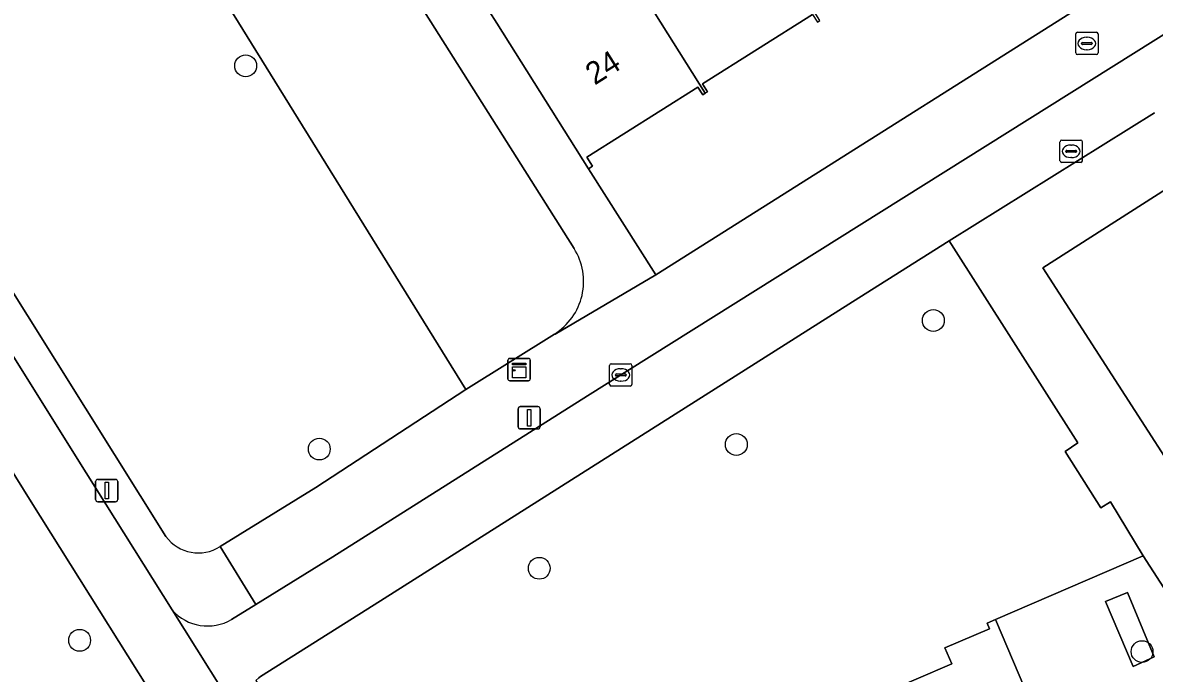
# Model space of a CAD drawing. Extents: x 160077 to 160948, y 386481 to 387498.
# Drawn here: x 160333.6 to 160384.3, y 386943.1 to 386972.2 of the extents above; entities that cross this region are included whole.
import ezdxf

# ---------------------------------------------------------------- set-up
doc = ezdxf.new("R2010")
doc.units = 0
for name, color, linetype in [('IMGEO_Berm_groen', 7, 'Continuous'), ('IMGEO_Boom', 7, 'Continuous'), ('IMGEO_Brandkraan', 7, 'Continuous'), ('IMGEO_Erf', 7, 'Continuous'), ('IMGEO_Fietspad_gesloten', 7, 'Continuous'), ('IMGEO_Fietspad_open', 7, 'Continuous'), ('IMGEO_Groenvoorziening', 7, 'Continuous'), ('IMGEO_Kast', 7, 'Continuous'), ('IMGEO_Kolk', 7, 'Continuous'), ('IMGEO_Lichtmast', 7, 'Continuous'), ('IMGEO_Pand', 7, 'Continuous'), ('IMGEO_Pand_nummerreeks', 7, 'Continuous'), ('IMGEO_Parkeervlak_open', 7, 'Continuous'), ('IMGEO_Rioolput', 7, 'Continuous'), ('IMGEO_Voetpad_open', 7, 'Continuous')]:
    doc.layers.add(name, color=color, linetype=linetype)

msp = doc.modelspace()

# ---------------------------------------------------------------- linework, layer by layer
at = {"layer": 'IMGEO_Berm_groen'}
msp.add_lwpolyline([(160381.755, 386874.497), (160381.719, 386874.568), (160381.199, 386875.409), (160373.722, 386887.333), (160362.991, 386904.447), (160352.34, 386921.431), (160340.92, 386939.644), (160333.952, 386950.749), (160331.8, 386954.187), (160320.577, 386972.116)], dxfattribs=at)
at = {"layer": 'IMGEO_Boom'}
for centre in [(160343.561, 386970.285), (160374.386, 386958.878), (160365.556, 386953.322), (160346.862, 386953.117), (160356.722, 386947.777), (160336.119, 386944.55), (160383.742, 386944.046)]:
    msp.add_circle(centre, 0.489, dxfattribs=at)
at = {"layer": 'IMGEO_Brandkraan'}
for p, q in [((160380.767, 386970.859), (160380.767, 386971.711)), ((160380.842, 386971.785), (160381.694, 386971.785)), ((160381.255, 386971.565), (160381.28, 386971.565)), ((160381.768, 386971.711), (160381.768, 386970.859)), ((160381.026, 386971.279), (160381.026, 386971.291)), ((160381.464, 386971.242), (160381.066, 386971.242)), ((160381.069, 386971.328), (160381.467, 386971.328)), ((160381.51, 386971.291), (160381.51, 386971.279)), ((160381.694, 386970.785), (160380.842, 386970.785)), ((160381.278, 386971.005), (160381.253, 386971.005))]:
    msp.add_line(p, q, dxfattribs=at)
for points in [[(160380.767, 386970.859), (160380.767, 386971.711)], [(160380.842, 386971.785), (160381.694, 386971.785)], [(160381.768, 386971.711), (160381.768, 386970.859)], [(160381.694, 386970.785), (160380.842, 386970.785)]]:
    msp.add_lwpolyline(points, dxfattribs=at)
for centre, radius, start, end in [((160380.844, 386971.709), 0.0765, 91.552, 178.448), ((160380.844, 386971.709), 0.0765, 91.552, 178.448), ((160381.692, 386971.709), 0.0765, 1.552, 88.448), ((160381.692, 386971.709), 0.0765, 1.552, 88.448), ((160381.066, 386971.288), 0.0403, 85.8775, 175.7526), ((160381.063, 386971.278), 0.0366, 178.938, 274.7102), ((160381.467, 386971.285), 0.043, 264.8664, 352.4533), ((160381.471, 386971.29), 0.0386, 1.7309, 96.639), ((160380.844, 386970.861), 0.0765, 181.552, 268.448), ((160380.844, 386970.861), 0.0765, 181.552, 268.448), ((160381.692, 386970.861), 0.0765, 271.552, 358.448), ((160381.692, 386970.861), 0.0765, 271.552, 358.448)]:
    msp.add_arc(centre, radius, start, end, dxfattribs=at)
for centre, major_axis, ratio, start_param, end_param in [((160381.254, 386971.285), (-0.387, 0.002), 0.722429, 4.712389, 7.853982), ((160381.279, 386971.285), (-0.39, 0.002), 0.717154, 1.570796, 4.712389)]:
    msp.add_ellipse(centre, major_axis=major_axis, ratio=ratio, start_param=start_param, end_param=end_param, dxfattribs=at)
at = {"layer": 'IMGEO_Erf'}
msp.add_lwpolyline([(160368.975, 386972.582), (160364.044, 386969.481), (160364.27, 386969.122), (160364.16, 386969.052), (160364.05, 386968.983), (160363.836, 386969.323), (160358.855, 386966.191), (160359.108, 386965.789), (160358.927, 386965.675), (160361.943, 386960.929), (160386.133, 386976.2)], dxfattribs=at)
at = {"layer": 'IMGEO_Fietspad_gesloten'}
for points in [[(160298.634, 387007.207), (160300.211, 387004.626), (160309.459, 386989.877), (160320.577, 386972.116), (160331.8, 386954.187), (160333.952, 386950.749), (160340.92, 386939.644), (160352.34, 386921.431), (160362.991, 386904.447), (160373.722, 386887.333), (160381.199, 386875.409), (160381.719, 386874.568), (160381.755, 386874.497), (160383.65, 386871.599), (160379.535, 386869.036)], [(160384.718, 386875.882), (160383.32, 386877.321), (160343.718, 386940.41), (160343.653, 386940.514), (160340.267, 386945.91), (160336.414, 386952.059), (160311.846, 386991.299)]]:
    msp.add_lwpolyline(points, dxfattribs=at)
at = {"layer": 'IMGEO_Fietspad_open'}
for points in [[(160392.767, 386976.747), (160358.891, 386955.508), (160347.47, 386948.297), (160344.021, 386946.162), (160342.931, 386945.487)], [(160371.041, 386959.892), (160375.091, 386962.445), (160384.296, 386968.171)], [(160344.012, 386942.759), (160344.15, 386942.871), (160344.231, 386942.938), (160349.319, 386946.138), (160371.041, 386959.892)], [(160340.267, 386945.91), (160343.653, 386940.514)]]:
    msp.add_lwpolyline(points, dxfattribs=at)
msp.add_arc((160341.854, 386947.307), 2.114, 221.3456, 300.6098, dxfattribs=at)
at = {"layer": 'IMGEO_Groenvoorziening'}
for points in [[(160334.305, 387000.002), (160333.091, 387001.929), (160330.043, 387000), (160327.145, 386998.17), (160353.425, 386955.793), (160357.402, 386958.269)], [(160358.281, 386962.101), (160334.305, 387000.002)], [(160327.145, 386998.17), (160319.488, 386993.382), (160314.349, 386990.13), (160337.688, 386952.871), (160339.984, 386949.196)], [(160342.413, 386948.748), (160346.707, 386951.396), (160353.425, 386955.793), (160327.145, 386998.17)], [(160382.328, 386950.748), (160381.9, 386950.487), (160380.291, 386953.014), (160380.863, 386953.4), (160375.091, 386962.445), (160371.041, 386959.892), (160349.319, 386946.138), (160344.231, 386942.938), (160344.15, 386942.871), (160344.012, 386942.759), (160385.024, 386877.426)], [(160387.832, 386876.495), (160402.136, 386879.409), (160401.949, 386880.328), (160396.287, 386879.166), (160394.179, 386884.089), (160389.777, 386882.204), (160367.51, 386934.196), (160372.585, 386936.369), (160370.414, 386941.438), (160375.213, 386943.493), (160374.906, 386944.211), (160376.91, 386945.068), (160376.8, 386945.325), (160377.168, 386945.482), (160383.799, 386948.34), (160382.328, 386950.748)]]:
    msp.add_lwpolyline(points, dxfattribs=at)
for centre, radius, start, end in [((160355.937, 386960.622), 2.771, 301.9024, 32.2591), ((160341.443, 386950.295), 1.827, 217.0074, 302.0924)]:
    msp.add_arc(centre, radius, start, end, dxfattribs=at)
at = {"layer": 'IMGEO_Kast'}
for p, q in [((160355.32, 386956.254), (160355.32, 386957.095)), ((160355.32, 386957.095), (160355.32, 386956.254)), ((160355.395, 386957.179), (160356.236, 386957.179)), ((160356.236, 386957.179), (160355.395, 386957.179)), ((160356.32, 386957.104), (160356.32, 386956.263)), ((160356.32, 386956.263), (160356.32, 386957.104)), ((160356.245, 386956.179), (160355.404, 386956.179)), ((160355.404, 386956.179), (160356.245, 386956.179))]:
    msp.add_line(p, q, dxfattribs=at)
for points in [[(160355.515, 386956.969), (160356.115, 386956.969), (160356.115, 386956.884), (160355.515, 386956.884), (160355.515, 386956.969)], [(160355.515, 386956.794), (160356.115, 386956.794), (160356.115, 386956.305), (160355.515, 386956.305), (160355.515, 386956.794)]]:
    msp.add_lwpolyline(points, dxfattribs=at)
msp.add_circle((160355.599, 386956.643), 0.0377, dxfattribs=at)
for centre, start, end in [((160355.398, 386957.101), 92.4484, 184.2845), ((160355.398, 386957.101), 92.4484, 184.2845), ((160356.242, 386957.101), 2.4484, 94.2845), ((160356.242, 386957.101), 2.4484, 94.2845), ((160355.398, 386956.257), 182.4484, 274.2845), ((160355.398, 386956.257), 182.4484, 274.2845), ((160356.242, 386956.257), 272.4484, 4.2845), ((160356.242, 386956.257), 272.4484, 4.2845)]:
    msp.add_arc(centre, 0.0779, start, end, dxfattribs=at)
at = {"layer": 'IMGEO_Kolk'}
for p, q in [((160359.875, 386956.012), (160359.875, 386956.864)), ((160359.95, 386956.938), (160360.802, 386956.938)), ((160360.876, 386956.864), (160360.876, 386956.012)), ((160360.134, 386956.432), (160360.134, 386956.444)), ((160360.572, 386956.395), (160360.174, 386956.395)), ((160360.177, 386956.481), (160360.575, 386956.481)), ((160360.363, 386956.718), (160360.388, 386956.718)), ((160360.618, 386956.444), (160360.618, 386956.432)), ((160360.802, 386955.938), (160359.95, 386955.938)), ((160360.386, 386956.158), (160360.361, 386956.158))]:
    msp.add_line(p, q, dxfattribs=at)
for points in [[(160359.875, 386956.012), (160359.875, 386956.864)], [(160359.95, 386956.938), (160360.802, 386956.938)], [(160360.876, 386956.864), (160360.876, 386956.012)], [(160360.802, 386955.938), (160359.95, 386955.938)]]:
    msp.add_lwpolyline(points, dxfattribs=at)
for centre, radius, start, end in [((160359.952, 386956.862), 0.0765, 91.552, 178.448), ((160359.952, 386956.862), 0.0765, 91.552, 178.448), ((160360.8, 386956.862), 0.0765, 1.552, 88.448), ((160360.8, 386956.862), 0.0765, 1.552, 88.448), ((160360.174, 386956.441), 0.0403, 85.8775, 175.7526), ((160360.171, 386956.431), 0.0366, 178.938, 274.7102), ((160360.575, 386956.438), 0.043, 264.8664, 352.4533), ((160360.579, 386956.443), 0.0386, 1.7309, 96.639), ((160359.952, 386956.014), 0.0765, 181.552, 268.448), ((160359.952, 386956.014), 0.0765, 181.552, 268.448), ((160360.8, 386956.014), 0.0765, 271.552, 358.448), ((160360.8, 386956.014), 0.0765, 271.552, 358.448)]:
    msp.add_arc(centre, radius, start, end, dxfattribs=at)
for centre, major_axis, ratio, start_param, end_param in [((160360.362, 386956.438), (-0.387, 0.002), 0.722429, 4.712389, 7.853982), ((160360.387, 386956.438), (-0.39, 0.002), 0.717154, 1.570796, 4.712389)]:
    msp.add_ellipse(centre, major_axis=major_axis, ratio=ratio, start_param=start_param, end_param=end_param, dxfattribs=at)
at = {"layer": 'IMGEO_Lichtmast'}
for p, q in [((160355.771, 386954.117), (160355.771, 386954.917)), ((160355.771, 386954.917), (160355.771, 386954.117)), ((160355.871, 386955.017), (160356.661, 386955.017)), ((160356.661, 386955.017), (160355.871, 386955.017)), ((160356.761, 386954.917), (160356.761, 386954.117)), ((160356.761, 386954.117), (160356.761, 386954.917)), ((160356.661, 386954.017), (160355.871, 386954.017)), ((160355.871, 386954.017), (160356.661, 386954.017)), ((160336.936, 386951.761), (160337.726, 386951.761)), ((160337.726, 386951.761), (160336.936, 386951.761)), ((160336.836, 386950.861), (160336.836, 386951.661)), ((160336.836, 386951.661), (160336.836, 386950.861)), ((160337.826, 386951.661), (160337.826, 386950.861)), ((160337.826, 386950.861), (160337.826, 386951.661)), ((160337.726, 386950.761), (160336.936, 386950.761)), ((160336.936, 386950.761), (160337.726, 386950.761))]:
    msp.add_line(p, q, dxfattribs=at)
for points in [[(160356.191, 386954.892), (160356.341, 386954.892), (160356.341, 386954.142), (160356.191, 386954.142), (160356.191, 386954.892)], [(160337.256, 386951.636), (160337.406, 386951.636), (160337.406, 386950.886), (160337.256, 386950.886), (160337.256, 386951.636)]]:
    msp.add_lwpolyline(points, dxfattribs=at)
for centre, start, end in [((160355.871, 386954.917), 90, 180), ((160355.871, 386954.917), 90, 180), ((160356.661, 386954.917), 0, 90), ((160356.661, 386954.917), 360, 90), ((160355.871, 386954.117), 180, 270), ((160355.871, 386954.117), 180, 270), ((160356.661, 386954.117), 270, 0), ((160356.661, 386954.117), 270, 0), ((160336.936, 386951.661), 90, 180), ((160336.936, 386951.661), 90, 180), ((160337.726, 386951.661), 0, 90), ((160337.726, 386951.661), 360, 90), ((160336.936, 386950.861), 180, 270), ((160336.936, 386950.861), 180, 270), ((160337.726, 386950.861), 270, 0), ((160337.726, 386950.861), 270, 0)]:
    msp.add_arc(centre, 0.1, start, end, dxfattribs=at)
at = {"layer": 'IMGEO_Pand'}
for points in [[(160365.066, 386979.066), (160359.897, 386975.838), (160364.16, 386969.052), (160364.27, 386969.122), (160364.044, 386969.481), (160368.975, 386972.582), (160369.188, 386972.244), (160369.305, 386972.318)], [(160359.897, 386975.838), (160359.81, 386975.783), (160358.839, 386977.329), (160356.148, 386975.636), (160356.635, 386974.86), (160354.139, 386973.29), (160354.826, 386972.197), (160358.927, 386965.675), (160359.108, 386965.789), (160358.855, 386966.191), (160363.836, 386969.323), (160364.05, 386968.983), (160364.16, 386969.052)], [(160396.703, 386885.17), (160398.079, 386881.957), (160401.233, 386883.307), (160399.716, 386886.848), (160398.538, 386886.344), (160376.545, 386937.697), (160377.683, 386938.184), (160379.502, 386938.998), (160379.667, 386938.611), (160380.034, 386938.768), (160379.763, 386939.403), (160379.506, 386939.294), (160378.482, 386941.694), (160378.738, 386941.803), (160377.168, 386945.482), (160376.8, 386945.325), (160376.91, 386945.068), (160374.906, 386944.211), (160375.213, 386943.493), (160370.414, 386941.438), (160372.585, 386936.369), (160367.51, 386934.196), (160389.777, 386882.204), (160394.179, 386884.089)]]:
    msp.add_lwpolyline(points, close=True, dxfattribs=at)
at = {"layer": 'IMGEO_Parkeervlak_open'}
msp.add_lwpolyline([(160385.916, 386965.458), (160379.288, 386961.228), (160386.077, 386950.727), (160387.305, 386948.746), (160389.414, 386950.096)], dxfattribs=at)
at = {"layer": 'IMGEO_Rioolput'}
for p, q in [((160380.139, 386966.954), (160380.991, 386966.954)), ((160380.064, 386966.028), (160380.064, 386966.88)), ((160380.323, 386966.448), (160380.323, 386966.46)), ((160380.366, 386966.497), (160380.764, 386966.497)), ((160380.552, 386966.734), (160380.577, 386966.734)), ((160380.807, 386966.46), (160380.807, 386966.448)), ((160381.065, 386966.88), (160381.065, 386966.028)), ((160380.991, 386965.954), (160380.139, 386965.954)), ((160380.761, 386966.411), (160380.363, 386966.411)), ((160380.575, 386966.174), (160380.55, 386966.174))]:
    msp.add_line(p, q, dxfattribs=at)
for points in [[(160380.139, 386966.954), (160380.991, 386966.954)], [(160380.064, 386966.028), (160380.064, 386966.88)], [(160381.065, 386966.88), (160381.065, 386966.028)], [(160380.991, 386965.954), (160380.139, 386965.954)]]:
    msp.add_lwpolyline(points, dxfattribs=at)
for centre, radius, start, end in [((160380.141, 386966.878), 0.0765, 91.552, 178.448), ((160380.141, 386966.878), 0.0765, 91.552, 178.448), ((160380.989, 386966.878), 0.0765, 1.552, 88.448), ((160380.989, 386966.878), 0.0765, 1.552, 88.448), ((160380.363, 386966.457), 0.0403, 85.8775, 175.7526), ((160380.36, 386966.447), 0.0366, 178.938, 274.7102), ((160380.764, 386966.454), 0.043, 264.8664, 352.4533), ((160380.768, 386966.459), 0.0386, 1.7309, 96.639), ((160380.141, 386966.03), 0.0765, 181.552, 268.448), ((160380.141, 386966.03), 0.0765, 181.552, 268.448), ((160380.989, 386966.03), 0.0765, 271.552, 358.448), ((160380.989, 386966.03), 0.0765, 271.552, 358.448)]:
    msp.add_arc(centre, radius, start, end, dxfattribs=at)
for centre, major_axis, ratio, start_param, end_param in [((160380.551, 386966.454), (-0.387, 0.002), 0.722429, 4.712389, 7.853982), ((160380.576, 386966.454), (-0.39, 0.002), 0.717154, 1.570796, 4.712389)]:
    msp.add_ellipse(centre, major_axis=major_axis, ratio=ratio, start_param=start_param, end_param=end_param, dxfattribs=at)
at = {"layer": 'IMGEO_Voetpad_open'}
for points in [[(160339.984, 386949.196), (160337.688, 386952.871), (160314.349, 386990.13), (160313.092, 386992.189), (160295.106, 387020.877)], [(160339.387, 387019.061), (160344.043, 387011.607), (160326.961, 387000.883), (160325.887, 387000.209), (160325.558, 387000.002), (160314.851, 386993.307), (160313.092, 386992.189), (160314.349, 386990.13), (160319.488, 386993.382), (160327.145, 386998.17), (160330.043, 387000), (160333.091, 387001.929), (160334.305, 387000.002), (160358.281, 386962.101)], [(160357.402, 386958.269), (160357.431, 386958.261), (160361.943, 386960.929), (160358.927, 386965.675), (160354.826, 386972.197), (160354.139, 386973.29), (160348.413, 386982.263), (160347.604, 386983.53), (160341.28, 386993.441), (160341.218, 386993.539), (160337.144, 387000), (160335.156, 387003.195), (160358.002, 387017.565)], [(160444.618, 387012.806), (160424.667, 387000.196), (160424.356, 387000), (160423.489, 386999.46), (160386.133, 386976.2), (160361.943, 386960.929), (160357.431, 386958.261), (160357.402, 386958.269), (160353.425, 386955.793), (160346.707, 386951.396), (160342.413, 386948.748), (160344.021, 386946.162), (160347.47, 386948.297), (160358.891, 386955.508), (160392.767, 386976.747), (160393.843, 386977.421), (160404.019, 386983.85), (160420.855, 386994.441)], [(160300.054, 387010.149), (160311.846, 386991.299), (160336.414, 386952.059), (160340.267, 386945.91)], [(160384.296, 386968.171), (160375.091, 386962.445), (160380.863, 386953.4), (160380.291, 386953.014), (160381.9, 386950.487), (160382.328, 386950.748), (160383.799, 386948.34), (160385.948, 386945.002), (160388.875, 386946.31), (160388.615, 386946.721), (160390.779, 386948.087)], [(160389.414, 386950.096), (160387.305, 386948.746), (160386.077, 386950.727), (160379.288, 386961.228), (160385.916, 386965.458)], [(160342.931, 386945.487), (160344.021, 386946.162), (160342.413, 386948.748)], [(160385.948, 386945.002), (160383.799, 386948.34), (160377.168, 386945.482), (160378.738, 386941.803), (160378.482, 386941.694), (160379.506, 386939.294), (160379.763, 386939.403), (160380.034, 386938.768), (160379.667, 386938.611), (160379.502, 386938.998), (160377.683, 386938.184), (160399.716, 386886.848)]]:
    msp.add_lwpolyline(points, dxfattribs=at)
for points in [[(160384.292, 386943.81), (160383.084, 386946.692), (160382.105, 386946.289), (160383.34, 386943.385)], [(160383.34, 386943.385), (160382.105, 386946.289), (160383.084, 386946.692), (160384.292, 386943.81)]]:
    msp.add_lwpolyline(points, close=True, dxfattribs=at)
for centre, radius, start, end in [((160355.937, 386960.622), 2.771, 301.9024, 32.2591), ((160341.443, 386950.295), 1.827, 217.0074, 302.0924), ((160341.854, 386947.307), 2.114, 221.3456, 300.6098)]:
    msp.add_arc(centre, radius, start, end, dxfattribs=at)

# ---------------------------------------------------------------- texts
at = {"layer": 'IMGEO_Pand_nummerreeks'}
msp.add_text('24', height=1, rotation=32.3034, dxfattribs=at).set_placement((160359.205, 386969.394))

doc.saveas('drawing.dxf')
